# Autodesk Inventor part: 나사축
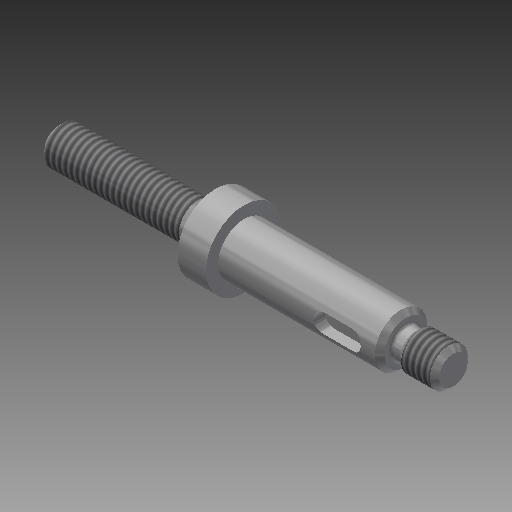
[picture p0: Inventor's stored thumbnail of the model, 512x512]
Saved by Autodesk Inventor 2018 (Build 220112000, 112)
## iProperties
Created: 2019-10
Part Number: 나사축
Material: 강철, 연강
Document SubType Name: Modeling
Designer: mduedu
Density: 1 g/cm^3
Appearance: 강철
Author: mduedu
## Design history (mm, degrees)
revolve "회전1" stored, may be unused: angle "d9" = 90 deg
sketch "스케치2"
  geometry: L1 (0, 4)-(0, -4) reference; L2 (0, -4)-(-33, -4) reference; L3 (-33, -4)-(-33, -8) reference; L4 (-33, -8)-(-39, -8) reference; L5 (-39, -8)-(-39, -5.5) reference; L6 (-39, -5.5)-(-73, -5.5) reference; L7 (-73, -5.5)-(-73, -3) reference; L8 (-76, -4)-(-83, -4) reference; L9 (-83, -4)-(-83, 4) reference; L10 (-83, 4)-(-76, 4) reference; L11 (-73, 3)-(-73, 5.5) reference; L12 (-73, 5.5)-(-39, 5.5) reference; L13 (-39, 5.5)-(-39, 8) reference; L14 (-39, 8)-(-33, 8) reference; L15 (-33, 8)-(-33, 4) reference; L16 (-33, 4)-(0, 4) reference; L17 (0, 0)-(-83, 0); L18 (-31, 3)-(-33, 3); L19 (-33, 3)-(-33, 4); L20 (-31, 3)-(-29.268, 4); L21 (-33, 4)-(-29.268, 4); L22 (-73, -3)-(-75, -3) reference; L23 (-75, -3)-(-76, -4) reference; L24 (-76, 4)-(-75, 3) reference; L25 (-75, 3)-(-73, 3) reference
  constraints: 10 end point, 1 collinear, 1 midpoint, 1 point on line, 1 vertical
  dimensions: "d13" = 1 distance between parallel lines of L18 L21; "d15" = 30 deg angle of L16 L20; "d17" = 2 distance of L18.start L18.end
revolve "회전2" sketch "스케치2" stored, may be unused: angle "d12" = 90 deg
feature "스레드1" dims "d18" = 10, "d19" = 0
feature "스레드2" dims "d20" = 7, "d21" = 0
chamfer "모따기1" distance "d22" = 1; stored, may be unused: second distance "d23" = 2, angle "d24" = 30 deg
chamfer "모따기2" distance "d25" = 1; stored, may be unused: second distance "d26" = 2, angle "d27" = 30 deg
sketch "스케치3"
  geometry: L1 (-31, -3)-(-33, -3) reference; L2 (-33, -3)-(-33, -8) reference; L3 (-33, -8)-(-39, -8) reference; L4 (-39, -8)-(-39, -5.5) reference; L5 (-39, -5.5)-(-72, -5.5) reference; L6 (-72, -5.5)-(-73, -4.5) reference; L7 (-73, -4.5)-(-73, -3) reference; L8 (-76, -4)-(-82, -4) reference; L9 (-82, -4)-(-83, -3) reference; L10 (-83, -3)-(-83, 3) reference; L11 (-83, 3)-(-82, 4) reference; L12 (-82, 4)-(-76, 4) reference; L13 (-73, 3)-(-73, 4.5) reference; L14 (-73, 4.5)-(-72, 5.5) reference; L15 (-72, 5.5)-(-39, 5.5) reference; L16 (-39, 5.5)-(-39, 8) reference; L17 (-39, 8)-(-33, 8) reference; L18 (-33, 8)-(-33, 3) reference; L19 (-33, 3)-(-31, 3) reference; L20 (-31, 3)-(-29.268, 4) reference; L21 (-29.268, 4)-(-1, 4) reference; L22 (-1, 4)-(0, 3) reference; L23 (0, 3)-(0, -3) reference; L24 (0, -3)-(-1, -4) reference; L25 (-1, -4)-(-29.268, -4) reference; L26 (-29.268, -4)-(-31, -3) reference; L27 (-59, 5.5)-(-69, 5.5); L28 (-69, 5.5)-(-69, 3); L29 (-69, 3)-(-59, 3); L30 (-59, 3)-(-59, 5.5); L31 (-73, -3)-(-75, -3) reference; L32 (-75, -3)-(-76, -4) reference; L33 (-76, 4)-(-75, 3) reference; L34 (-75, 3)-(-73, 3) reference; 1 further point
  constraints: 8 end point, 2 parallel, 1 horizontal, 1 perpendicular, 1 point on line
  dimensions: "d28" = 20 distance between parallel lines of L30 L16; "d29" = 10 distance of L27.start L27.end; "d30" = 2.5 distance of L27.end L28.end
extrude "돌출1" cut sketch "스케치3" stored distance "d31" = 4; taper "d32" = 0 deg
fillet "모깎기1"
fillet "모깎기2"
fillet "모깎기3" dims "d36" = 0.6
node "솔리드1"
sketch "스케치1"
  geometry: L1 (0, 0)-(33, 0); L2 (33, 0)-(33, 4); L3 (33, 4)-(0, 4); L4 (0, 4)-(0, 0); L5 (33, 0)-(39, 0); L6 (39, 0)-(39, 8); L7 (39, 8)-(33, 8); L8 (33, 8)-(33, 0); L9 (39, 0)-(73, 0); L10 (73, 0)-(73, 5.5); L11 (73, 5.5)-(39, 5.5); L12 (39, 5.5)-(39, 0); L13 (73, 0)-(83, 0); L14 (83, 0)-(83, 4); L15 (83, 4)-(76, 4); L16 (73, 4)-(73, 0); L17 (73, 3)-(75, 3); L18 (75, 3)-(76, 4)
  constraints: 36 end point, 8 parallel, 5 perpendicular, 4 horizontal, 1 point on line
  dimensions: "d0" = 83 distance between parallel lines of L14 L4; "d2" = 8 diameter of L15 L13; "d3" = 11 diameter of L11 L9; "d4" = 16 diameter of L7 L5; "d5" = 8 diameter of L3 L1; "d6" = 33 distance of L2.end L3.end; "d7" = 6 distance of L6.end L7.end; "d8" = 40 distance between parallel lines of L10 L8; "d33" = 2 distance of L17.start L17.end; "d34" = 135 deg angle of L18 L17; "d35" = 6 diameter of L17 L13 (computed from d2)
node "절단 모서리 투영1"
node "절단 모서리 투영2"
